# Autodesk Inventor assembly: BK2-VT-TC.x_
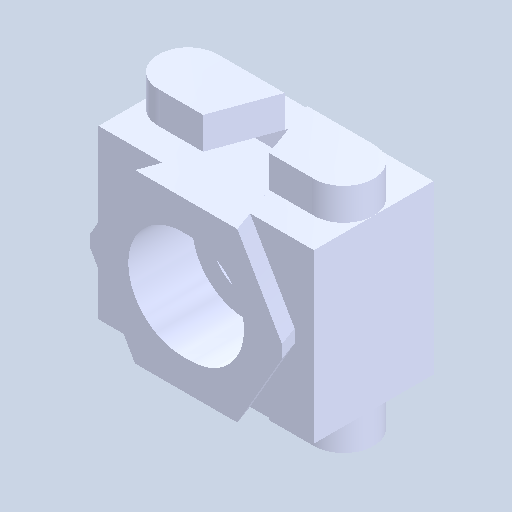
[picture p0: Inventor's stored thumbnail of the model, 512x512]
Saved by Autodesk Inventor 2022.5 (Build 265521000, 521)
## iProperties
Created: 2024-05
Part Number: BK2-VT-TC.x_
Document SubType Name: Assembly
Designer: ImaoCorp
Author: ImaoCorp
Sending System: SOLIDWORKS 2022-2022290
MC: AMD64
MC_MODEL: Intel64 Family 6 Model 60 Stepping 3, GenuineIntel
OS: Windows_NT
FRU: Parasolid Version 33.1, build 260,  4-25-2022
FORMAT: text
GUISE: transmit
KEY: FILEBK2-VT-TC.x_t
DATE: Mon May 20 16:29:22 2024
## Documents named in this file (4)
- X:\14_SW2022-Inv2022\保留中\ok-vise\データ\bk2-vt-tc\BK2-VT-TC.x_.iam
- X:\14_SW2022-Inv2022\保留中\ok-vise\データ\bk2-vt-tc\BK2-VT-TC_01.ipt
- X:\14_SW2022-Inv2022\保留中\ok-vise\データ\bk2-vt-tc\BK2-VT-TC_02.ipt
- X:\14_SW2022-Inv2022\保留中\ok-vise\データ\bk2-vt-tc\BK2-VT-TC_03.ipt
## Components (3 placed, 3 different names)
1. BK2-VT-TC_01
2. BK2-VT-TC_02
3. BK2-VT-TC_03
